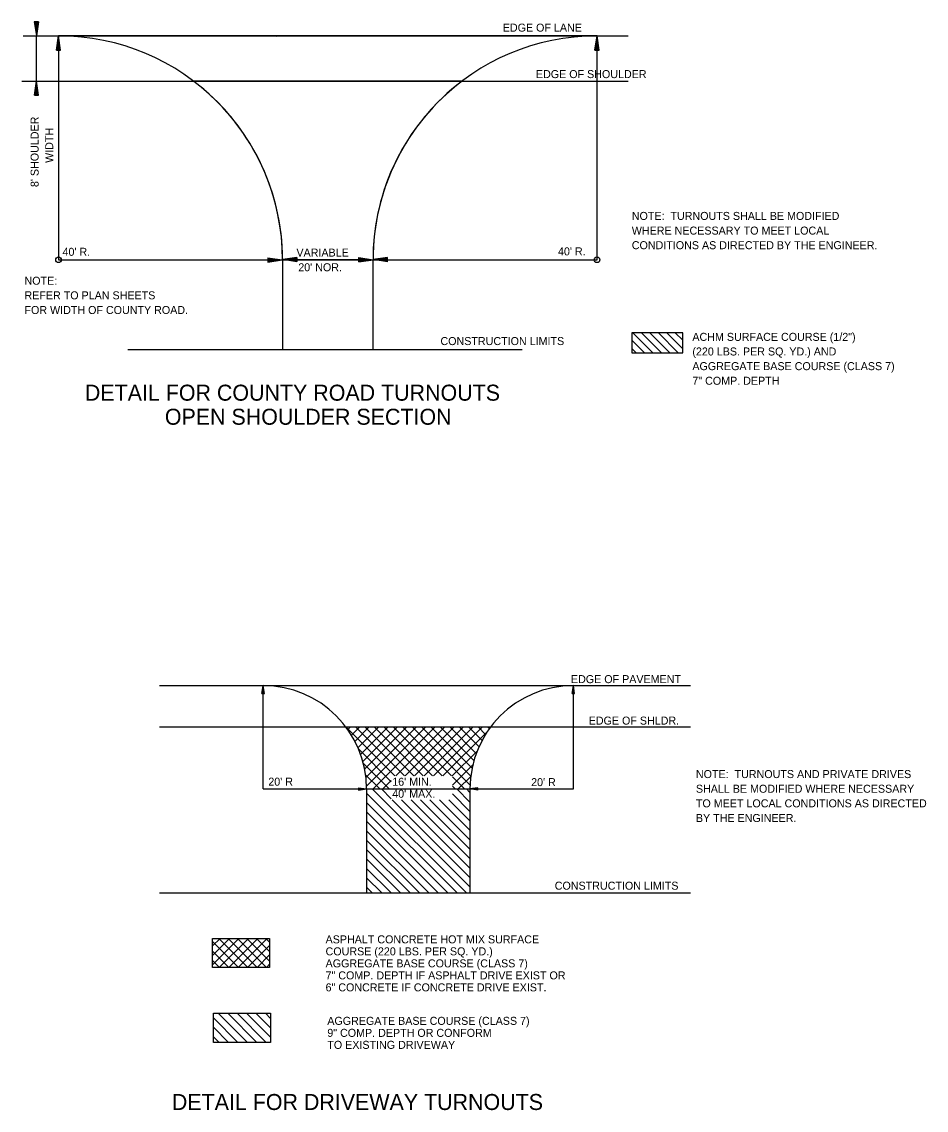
# Model space of a CAD drawing. Extents: x 3314 to 1767681, y -207 to 581440.
# Drawn here: x 3635 to 3770.6, y -176.7 to -13.5 of the extents above; entities that cross this region are included whole.
import ezdxf

# ---------------------------------------------------------------- set-up
doc = ezdxf.new("R2010")
doc.units = 0
for name, color, linetype in [('Default', 7, 'Continuous'), ('R_Border PE', 7, 'Continuous'), ('T_Drafting', 7, 'Continuous')]:
    doc.layers.add(name, color=color, linetype=linetype)

msp = doc.modelspace()

# ---------------------------------------------------------------- linework, layer by layer
at = {"layer": 'Default'}
for p, q in [((3636.92, -13.46), (3637.24, -15.58)), ((3637.56, -13.46), (3636.92, -13.46)), ((3636.97, -13.46), (3637.24, -15.23)), ((3637.03, -13.46), (3637.24, -14.86)), ((3637.09, -13.46), (3637.24, -14.51)), ((3637.14, -13.46), (3637.24, -14.15)), ((3637.19, -13.46), (3637.24, -13.8)), ((3637.56, -13.46), (3637.24, -15.58)), ((3637.34, -13.46), (3637.24, -14.15)), ((3637.46, -13.46), (3637.24, -14.86)), ((3637.51, -13.46), (3637.24, -15.23)), ((3637.4, -13.46), (3637.24, -14.51)), ((3637.29, -13.46), (3637.24, -13.8)), ((3635.23, -15.58), (3725.93, -15.58)), ((3637.24, -22.36), (3637.24, -15.58)), ((3640.23, -17.7), (3640.56, -15.58)), ((3640.29, -17.7), (3640.56, -15.94)), ((3640.34, -17.7), (3640.56, -16.3)), ((3721.27, -15.58), (3640.55, -15.58)), ((3640.87, -17.7), (3640.56, -15.58)), ((3640.56, -15.58), (3640.56, -49.16)), ((3640.82, -17.7), (3640.56, -15.94)), ((3640.76, -17.7), (3640.56, -16.3)), ((3673.22, -15.65), (3673.25, -15.56)), ((3673.25, -15.59), (3673.22, -15.65)), ((3673.22, -15.65), (3673.25, -15.62)), ((3720.95, -17.7), (3721.27, -15.58)), ((3721, -17.7), (3721.27, -15.94)), ((3721.06, -17.7), (3721.27, -16.3)), ((3721.59, -17.7), (3721.27, -15.58)), ((3721.27, -49.16), (3721.27, -15.58)), ((3721.54, -17.7), (3721.27, -15.94)), ((3721.48, -17.7), (3721.27, -16.3)), ((3640.23, -17.7), (3640.87, -17.7)), ((3640.39, -17.7), (3640.56, -16.65)), ((3640.45, -17.7), (3640.56, -17.01)), ((3640.5, -17.7), (3640.56, -17.37)), ((3640.71, -17.7), (3640.56, -16.65)), ((3640.66, -17.7), (3640.56, -17.01)), ((3640.6, -17.7), (3640.56, -17.37)), ((3720.95, -17.7), (3721.59, -17.7)), ((3721.11, -17.7), (3721.27, -16.66)), ((3721.17, -17.7), (3721.27, -17.02)), ((3721.22, -17.7), (3721.27, -17.37)), ((3721.42, -17.7), (3721.27, -16.66)), ((3721.38, -17.7), (3721.27, -17.02)), ((3721.32, -17.7), (3721.27, -17.37)), ((3635.05, -22.36), (3725.93, -22.36)), ((3636.93, -24.48), (3637.24, -22.36)), ((3636.98, -24.48), (3637.24, -22.72)), ((3637.56, -24.48), (3637.24, -22.36)), ((3637.51, -24.48), (3637.24, -22.72)), ((3701.04, -22.36), (3660.78, -22.36)), ((3636.93, -24.48), (3637.56, -24.48)), ((3637.03, -24.48), (3637.24, -23.08)), ((3637.08, -24.48), (3637.24, -23.44)), ((3637.14, -24.48), (3637.24, -23.8)), ((3637.19, -24.48), (3637.24, -24.15)), ((3637.46, -24.48), (3637.24, -23.08)), ((3637.4, -24.48), (3637.24, -23.44)), ((3637.35, -24.48), (3637.24, -23.8)), ((3637.29, -24.48), (3637.24, -24.15)), ((3671.93, -48.86), (3674.05, -49.18)), ((3671.93, -48.86), (3671.93, -49.5)), ((3671.93, -48.91), (3673.69, -49.18)), ((3671.93, -48.96), (3673.33, -49.18)), ((3676.28, -48.81), (3674.16, -49.13)), ((3674.16, -49.13), (3676.28, -48.81)), ((3676.28, -48.86), (3674.52, -49.13)), ((3676.28, -48.92), (3674.88, -49.13)), ((3676.28, -48.97), (3675.23, -49.13)), ((3676.28, -49.45), (3676.28, -48.81)), ((3676.28, -48.81), (3676.28, -49.16)), ((3685.57, -48.84), (3687.69, -49.16)), ((3685.57, -48.84), (3685.57, -49.48)), ((3685.57, -49.16), (3685.57, -48.84)), ((3685.57, -48.84), (3687.69, -49.16)), ((3685.57, -48.9), (3687.34, -49.16)), ((3685.57, -48.95), (3686.97, -49.16)), ((3689.84, -48.81), (3687.72, -49.13)), ((3689.84, -48.86), (3688.08, -49.13)), ((3689.84, -48.92), (3688.44, -49.13)), ((3689.84, -48.97), (3688.79, -49.13)), ((3689.84, -49.45), (3689.84, -48.81)), ((3640.55, -49.16), (3674.13, -49.16)), ((3671.93, -49.02), (3672.97, -49.18)), ((3671.93, -49.08), (3672.61, -49.18)), ((3671.93, -49.13), (3672.26, -49.18)), ((3671.93, -49.5), (3674.05, -49.18)), ((3671.93, -49.28), (3672.61, -49.18)), ((3671.93, -49.39), (3673.33, -49.18)), ((3671.93, -49.45), (3673.69, -49.18)), ((3671.93, -49.33), (3672.97, -49.18)), ((3671.93, -49.23), (3672.26, -49.18)), ((3674.13, -49.16), (3674.36, -49.16)), ((3674.36, -49.16), (3674.13, -49.16)), ((3674.14, -49.16), (3674.14, -62.62)), ((3674.14, -49.16), (3687.69, -49.16)), ((3674.14, -49.16), (3687.69, -49.16)), ((3674.14, -49.16), (3674.14, -62.62)), ((3676.28, -49.45), (3674.16, -49.13)), ((3674.36, -49.16), (3674.16, -49.13)), ((3676.28, -49.44), (3674.36, -49.16)), ((3676.28, -49.39), (3674.52, -49.13)), ((3676.28, -49.34), (3674.88, -49.13)), ((3676.28, -49.29), (3675.23, -49.13)), ((3676.28, -49.02), (3675.59, -49.13)), ((3676.28, -49.23), (3675.59, -49.13)), ((3676.28, -49.08), (3675.94, -49.13)), ((3676.28, -49.18), (3675.94, -49.13)), ((3676.28, -49.16), (3685.57, -49.16)), ((3685.57, -49.16), (3676.28, -49.16)), ((3676.28, -49.16), (3676.28, -49.44)), ((3685.57, -49.01), (3686.62, -49.16)), ((3685.57, -49.06), (3686.26, -49.16)), ((3685.57, -49.11), (3685.9, -49.16)), ((3685.57, -49.48), (3687.69, -49.16)), ((3685.57, -49.27), (3686.26, -49.16)), ((3685.57, -49.37), (3686.97, -49.16)), ((3685.57, -49.43), (3687.34, -49.16)), ((3685.57, -49.32), (3686.62, -49.16)), ((3685.57, -49.21), (3685.9, -49.16)), ((3687.69, -49.16), (3685.57, -49.48)), ((3685.57, -49.48), (3685.57, -49.16)), ((3687.69, -62.62), (3687.69, -49.16)), ((3687.69, -49.16), (3721.27, -49.16)), ((3687.69, -62.62), (3687.69, -49.16)), ((3689.84, -49.45), (3687.72, -49.13)), ((3689.84, -49.39), (3688.08, -49.13)), ((3689.84, -49.34), (3688.44, -49.13)), ((3689.84, -49.29), (3688.79, -49.13)), ((3689.84, -49.02), (3689.15, -49.13)), ((3689.84, -49.23), (3689.15, -49.13)), ((3689.84, -49.08), (3689.5, -49.13)), ((3689.84, -49.18), (3689.5, -49.13)), ((3650.93, -62.62), (3710.05, -62.62)), ((3674.13, -62.62), (3687.69, -62.62))]:
    msp.add_line(p, q, dxfattribs=at)
msp.add_lwpolyline([(3726.48, -60.11), (3726.48, -63.1), (3734.11, -63.1), (3734.11, -60.11)], close=True, dxfattribs=at)
for points in [[(3726.66, -60.11), (3729.65, -63.1)], [(3727.93, -60.11), (3730.91, -63.1)], [(3729.19, -60.11), (3732.18, -63.1)], [(3730.46, -60.11), (3733.45, -63.1)], [(3731.73, -60.11), (3734.11, -62.49)], [(3732.99, -60.11), (3734.11, -61.23)], [(3726.48, -61.21), (3728.38, -63.1)], [(3726.48, -62.48), (3727.11, -63.1)]]:
    msp.add_lwpolyline(points, dxfattribs=at)
for centre, radius in [((3640.55, -49.16), 0.423), ((3721.27, -49.16), 0.424)]:
    msp.add_circle(centre, radius, dxfattribs=at)
for centre, start, end in [((3640.55, -49.16), 0, 90), ((3640.55, -49.16), 0, 90), ((3721.27, -49.16), 90, 180), ((3721.27, -49.16), 90, 180), ((3640.55, -49.16), 0.0007, 52.9538), ((3721.27, -49.16), 127.0464, 180)]:
    msp.add_arc(centre, 33.58, start, end, dxfattribs=at)
at = {"layer": 'R_Border PE'}
for p, q in [((3655.71, -113.02), (3735.26, -113.02)), ((3671.23, -128.52), (3671.23, -113.02)), ((3717.72, -128.52), (3717.72, -113.02)), ((3655.71, -119.22), (3735.26, -119.22)), ((3690.98, -126.56), (3683.64, -119.22)), ((3683.9, -119.62), (3684.3, -119.22)), ((3684.46, -120.47), (3685.71, -119.22)), ((3684.97, -121.38), (3687.13, -119.22)), ((3692.39, -126.56), (3685.05, -119.22)), ((3685.43, -122.33), (3688.54, -119.22)), ((3685.83, -123.35), (3689.96, -119.22)), ((3686.17, -124.42), (3691.37, -119.22)), ((3686.44, -125.57), (3692.78, -119.22)), ((3693.81, -126.56), (3686.46, -119.22)), ((3686.62, -126.8), (3694.2, -119.22)), ((3686.71, -128.12), (3695.61, -119.22)), ((3687.73, -128.52), (3697.03, -119.22)), ((3695.22, -126.56), (3687.88, -119.22)), ((3696.63, -126.56), (3689.29, -119.22)), ((3698.05, -126.56), (3690.71, -119.22)), ((3691.1, -126.56), (3698.44, -119.22)), ((3699.46, -126.56), (3692.12, -119.22)), ((3692.51, -126.56), (3699.85, -119.22)), ((3702.24, -127.93), (3693.54, -119.22)), ((3693.93, -126.56), (3701.27, -119.22)), ((3702.35, -126.62), (3694.95, -119.22)), ((3695.34, -126.56), (3702.68, -119.22)), ((3702.55, -125.4), (3696.36, -119.22)), ((3696.76, -126.56), (3704.1, -119.22)), ((3702.82, -124.27), (3697.78, -119.22)), ((3698.17, -126.56), (3704.89, -119.84)), ((3703.17, -123.2), (3699.19, -119.22)), ((3703.58, -122.19), (3700.61, -119.22)), ((3704.04, -121.25), (3702.02, -119.22)), ((3704.56, -120.35), (3703.43, -119.22)), ((3705.13, -119.5), (3704.85, -119.22)), ((3690.43, -127.43), (3685.5, -122.5)), ((3699.58, -126.56), (3703.31, -122.84)), ((3690.11, -128.52), (3686.22, -124.64)), ((3699.6, -127.96), (3702.66, -124.9)), ((3688.69, -128.52), (3686.58, -126.41)), ((3689.14, -128.52), (3690.43, -127.23)), ((3701.42, -128.52), (3699.6, -126.7)), ((3700.46, -128.52), (3702.35, -126.63)), ((3671.23, -128.52), (3686.73, -128.52)), ((3686.73, -128.52), (3686.73, -144.12)), ((3686.73, -128.52), (3702.22, -128.52)), ((3702.22, -143.21), (3687.54, -128.52)), ((3690.43, -130), (3688.95, -128.52)), ((3690.43, -128.59), (3690.36, -128.52)), ((3700, -128.52), (3699.6, -128.12)), ((3702.22, -130.48), (3700.26, -128.52)), ((3702.22, -129.07), (3701.68, -128.52)), ((3702.22, -128.52), (3702.22, -144.12)), ((3702.22, -128.52), (3717.72, -128.52)), ((3701.72, -144.12), (3686.73, -129.13)), ((3700.31, -144.12), (3686.73, -130.54)), ((3702.22, -141.79), (3690.57, -130.14)), ((3702.22, -140.38), (3691.98, -130.14)), ((3702.22, -138.97), (3693.39, -130.14)), ((3702.22, -137.55), (3694.81, -130.14)), ((3702.22, -136.14), (3696.22, -130.14)), ((3702.22, -134.72), (3697.64, -130.14)), ((3702.22, -133.31), (3699.05, -130.14)), ((3702.22, -131.89), (3699.6, -129.27)), ((3698.89, -144.12), (3686.73, -131.95)), ((3697.48, -144.12), (3686.73, -133.37)), ((3696.06, -144.12), (3686.73, -134.78)), ((3694.65, -144.12), (3686.73, -136.2)), ((3693.24, -144.12), (3686.73, -137.61)), ((3691.82, -144.12), (3686.73, -139.02)), ((3690.41, -144.12), (3686.73, -140.44)), ((3688.99, -144.12), (3686.73, -141.85)), ((3687.58, -144.12), (3686.73, -143.27)), ((3655.71, -144.12), (3735.26, -144.12)), ((3663.64, -152.07), (3664.78, -150.93)), ((3663.64, -153.48), (3666.19, -150.93)), ((3663.64, -154.9), (3667.6, -150.93)), ((3667.51, -155.29), (3663.64, -151.42)), ((3668.92, -155.29), (3664.56, -150.93)), ((3664.65, -155.29), (3669.02, -150.93)), ((3670.34, -155.29), (3665.97, -150.93)), ((3666.07, -155.29), (3670.43, -150.93)), ((3671.75, -155.29), (3667.39, -150.93)), ((3667.48, -155.29), (3671.85, -150.93)), ((3672.2, -154.33), (3668.8, -150.93)), ((3672.2, -152.91), (3670.22, -150.93)), ((3672.2, -151.5), (3671.63, -150.93)), ((3666.1, -155.29), (3663.64, -152.84)), ((3668.9, -155.29), (3672.2, -151.99)), ((3670.31, -155.29), (3672.2, -153.41)), ((3664.68, -155.29), (3663.64, -154.25)), ((3671.73, -155.29), (3672.2, -154.82)), ((3667.44, -166.53), (3663.77, -162.86)), ((3668.86, -166.53), (3664.49, -162.16)), ((3670.27, -166.53), (3665.91, -162.16)), ((3671.69, -166.53), (3667.32, -162.16)), ((3672.34, -165.76), (3668.74, -162.16)), ((3672.34, -164.35), (3670.15, -162.16)), ((3672.34, -162.93), (3671.56, -162.16)), ((3666.03, -166.53), (3663.77, -164.27)), ((3664.62, -166.53), (3663.77, -165.68))]:
    msp.add_line(p, q, dxfattribs=at)
for points in [[(3663.64, -150.93), (3672.2, -150.93), (3672.2, -155.29), (3663.64, -155.29)], [(3663.77, -162.16), (3672.34, -162.16), (3672.34, -166.53), (3663.77, -166.53)]]:
    msp.add_lwpolyline(points, close=True, dxfattribs=at)
for centre, start, end in [((3671.23, -128.52), 0, 90), ((3717.72, -128.52), 90, 180)]:
    msp.add_arc(centre, 15.5, start, end, dxfattribs=at)
at = {"layer": 'T_Drafting'}
for p, q in [((3671.05, -114.22), (3671.23, -113.02)), ((3671.05, -114.22), (3671.23, -113.02)), ((3671.05, -114.22), (3671.41, -114.22)), ((3671.05, -114.22), (3671.41, -114.22)), ((3671.08, -114.22), (3671.23, -113.22)), ((3671.08, -114.22), (3671.23, -113.22)), ((3671.11, -114.22), (3671.23, -113.43)), ((3671.11, -114.22), (3671.23, -113.43)), ((3671.14, -114.22), (3671.23, -113.63)), ((3671.14, -114.22), (3671.23, -113.63)), ((3671.17, -114.22), (3671.23, -113.83)), ((3671.17, -114.22), (3671.23, -113.83)), ((3671.2, -114.22), (3671.23, -114.03)), ((3671.2, -114.22), (3671.23, -114.03)), ((3671.41, -114.22), (3671.23, -113.02)), ((3671.41, -114.22), (3671.23, -113.02)), ((3671.38, -114.22), (3671.23, -113.22)), ((3671.38, -114.22), (3671.23, -113.22)), ((3671.35, -114.22), (3671.23, -113.43)), ((3671.35, -114.22), (3671.23, -113.43)), ((3671.32, -114.22), (3671.23, -113.63)), ((3671.32, -114.22), (3671.23, -113.63)), ((3671.29, -114.22), (3671.23, -113.83)), ((3671.29, -114.22), (3671.23, -113.83)), ((3671.26, -114.22), (3671.23, -114.03)), ((3671.26, -114.22), (3671.23, -114.03)), ((3717.54, -114.22), (3717.72, -113.02)), ((3717.54, -114.22), (3717.72, -113.02)), ((3717.54, -114.22), (3717.9, -114.22)), ((3717.54, -114.22), (3717.9, -114.22)), ((3717.57, -114.22), (3717.72, -113.22)), ((3717.57, -114.22), (3717.72, -113.22)), ((3717.6, -114.22), (3717.72, -113.43)), ((3717.6, -114.22), (3717.72, -113.43)), ((3717.63, -114.22), (3717.72, -113.63)), ((3717.63, -114.22), (3717.72, -113.63)), ((3717.66, -114.22), (3717.72, -113.83)), ((3717.66, -114.22), (3717.72, -113.83)), ((3717.69, -114.22), (3717.72, -114.03)), ((3717.69, -114.22), (3717.72, -114.03)), ((3717.9, -114.22), (3717.72, -113.02)), ((3717.9, -114.22), (3717.72, -113.02)), ((3717.87, -114.22), (3717.72, -113.22)), ((3717.87, -114.22), (3717.72, -113.22)), ((3717.84, -114.22), (3717.72, -113.43)), ((3717.84, -114.22), (3717.72, -113.43)), ((3717.81, -114.22), (3717.72, -113.63)), ((3717.81, -114.22), (3717.72, -113.63)), ((3717.78, -114.22), (3717.72, -113.83)), ((3717.78, -114.22), (3717.72, -113.83)), ((3717.75, -114.22), (3717.72, -114.03)), ((3717.75, -114.22), (3717.72, -114.03)), ((3685.53, -128.34), (3686.73, -128.52)), ((3685.53, -128.34), (3685.53, -128.7)), ((3685.53, -128.34), (3686.73, -128.52)), ((3685.53, -128.34), (3685.53, -128.7)), ((3685.53, -128.37), (3686.53, -128.52)), ((3685.53, -128.37), (3686.53, -128.52)), ((3685.53, -128.4), (3686.32, -128.52)), ((3685.53, -128.4), (3686.32, -128.52)), ((3685.53, -128.43), (3686.12, -128.52)), ((3685.53, -128.43), (3686.12, -128.52)), ((3685.53, -128.46), (3685.92, -128.52)), ((3685.53, -128.46), (3685.92, -128.52)), ((3685.53, -128.49), (3685.72, -128.52)), ((3685.53, -128.49), (3685.72, -128.52)), ((3685.53, -128.7), (3686.73, -128.52)), ((3685.53, -128.58), (3685.92, -128.52)), ((3685.53, -128.64), (3686.32, -128.52)), ((3685.53, -128.67), (3686.53, -128.52)), ((3685.53, -128.61), (3686.12, -128.52)), ((3685.53, -128.55), (3685.72, -128.52)), ((3685.53, -128.7), (3686.73, -128.52)), ((3685.53, -128.58), (3685.92, -128.52)), ((3685.53, -128.64), (3686.32, -128.52)), ((3685.53, -128.67), (3686.53, -128.52)), ((3685.53, -128.61), (3686.12, -128.52)), ((3685.53, -128.55), (3685.72, -128.52)), ((3703.42, -128.34), (3702.22, -128.52)), ((3703.42, -128.34), (3702.22, -128.52)), ((3703.42, -128.7), (3702.22, -128.52)), ((3703.42, -128.7), (3702.22, -128.52)), ((3703.42, -128.37), (3702.42, -128.52)), ((3703.42, -128.37), (3702.42, -128.52)), ((3703.42, -128.67), (3702.42, -128.52)), ((3703.42, -128.67), (3702.42, -128.52)), ((3703.42, -128.4), (3702.63, -128.52)), ((3703.42, -128.4), (3702.63, -128.52)), ((3703.42, -128.64), (3702.63, -128.52)), ((3703.42, -128.64), (3702.63, -128.52)), ((3703.42, -128.43), (3702.83, -128.52)), ((3703.42, -128.43), (3702.83, -128.52)), ((3703.42, -128.61), (3702.83, -128.52)), ((3703.42, -128.61), (3702.83, -128.52)), ((3703.42, -128.46), (3703.03, -128.52)), ((3703.42, -128.46), (3703.03, -128.52)), ((3703.42, -128.58), (3703.03, -128.52)), ((3703.42, -128.58), (3703.03, -128.52)), ((3703.42, -128.49), (3703.23, -128.52)), ((3703.42, -128.49), (3703.23, -128.52)), ((3703.42, -128.55), (3703.23, -128.52)), ((3703.42, -128.55), (3703.23, -128.52)), ((3703.42, -128.7), (3703.42, -128.34)), ((3703.42, -128.7), (3703.42, -128.34))]:
    msp.add_line(p, q, dxfattribs=at)

# ---------------------------------------------------------------- texts
at = {"layer": 'Default'}
for s, height, p in [('EDGE OF LANE', 1.2, (3707.14, -14.94)), ('EDGE OF SHOULDER', 1.2, (3712.11, -21.91)), ('NOTE:  TURNOUTS SHALL BE MODIFIED ', 1.2, (3726.48, -43.18)), ('WHERE NECESSARY TO MEET LOCAL ', 1.2, (3726.48, -45.38)), ("40' R.", 1.2, (3715.42, -48.5)), ('CONDITIONS AS DIRECTED BY THE ENGINEER.', 1.2, (3726.48, -47.57)), ("40' R.", 1.2, (3641.15, -48.56)), ('VARIABLE', 1.2, (3676.21, -48.68)), ("20' NOR.", 1.2, (3676.49, -50.88)), ('NOTE:', 1.2, (3635.45, -52.9)), ('REFER TO PLAN SHEETS', 1.2, (3635.45, -55.09)), ('FOR WIDTH OF COUNTY ROAD.', 1.2, (3635.45, -57.29)), ('ACHM SURFACE COURSE (1/2") ', 1.2, (3735.56, -61.32)), ('CONSTRUCTION LIMITS', 1.2, (3697.8, -61.95)), ('(220 LBS. PER SQ. YD.) AND ', 1.2, (3735.56, -63.51)), ('AGGREGATE BASE COURSE (CLASS 7)', 1.2, (3735.56, -65.71)), ('7" COMP. DEPTH', 1.2, (3735.56, -67.9)), ('DETAIL FOR COUNTY ROAD TURNOUTS', 2.4, (3644.5, -70.29)), ('OPEN SHOULDER SECTION', 2.4, (3656.49, -73.9)), ('NOTE:  TURNOUTS AND PRIVATE DRIVES', 1.2, (3736.09, -126.89)), ('SHALL BE MODIFIED WHERE NECESSARY', 1.2, (3736.09, -129.09)), ('TO MEET LOCAL CONDITIONS AS DIRECTED', 1.2, (3736.09, -131.28)), ('BY THE ENGINEER.', 1.2, (3736.09, -133.48))]:
    msp.add_text(s, height=height, dxfattribs=at).set_placement(p)
for s, p in [("8' SHOULDER", (3637.57, -38.25)), ('WIDTH', (3639.76, -34.63))]:
    msp.add_text(s, height=1.2, rotation=90, dxfattribs=at).set_placement(p)
at = {"layer": 'R_Border PE'}
for s, height, p in [('EDGE OF PAVEMENT', 1.2, (3717.36, -112.65)), ('EDGE OF SHLDR.', 1.2, (3720.02, -118.87)), ("20' R", 1.2, (3672, -128.03)), ("16' MIN.", 1.2, (3690.57, -128.04)), ("20' R", 1.2, (3711.39, -128.1)), ("40' MAX.", 1.2, (3690.57, -129.84)), ('CONSTRUCTION LIMITS', 1.2, (3714.93, -143.63)), ('ASPHALT CONCRETE HOT MIX SURFACE', 1.2, (3680.58, -151.68)), ('COURSE (220 LBS. PER SQ. YD.) ', 1.2, (3680.58, -153.48)), ('AGGREGATE BASE COURSE (CLASS 7) ', 1.2, (3680.58, -155.28)), ('7" COMP. DEPTH IF ASPHALT DRIVE EXIST OR', 1.2, (3680.58, -157.08)), ('6" CONCRETE IF CONCRETE DRIVE EXIST.', 1.2, (3680.58, -158.88)), ('AGGREGATE BASE COURSE (CLASS 7)', 1.2, (3680.84, -163.9)), ('9" COMP. DEPTH OR CONFORM', 1.2, (3680.84, -165.7)), ('TO EXISTING DRIVEWAY', 1.2, (3680.84, -167.5)), ('DETAIL FOR DRIVEWAY TURNOUTS', 2.4, (3657.54, -176.67))]:
    msp.add_text(s, height=height, dxfattribs=at).set_placement(p)

doc.saveas('drawing.dxf')
